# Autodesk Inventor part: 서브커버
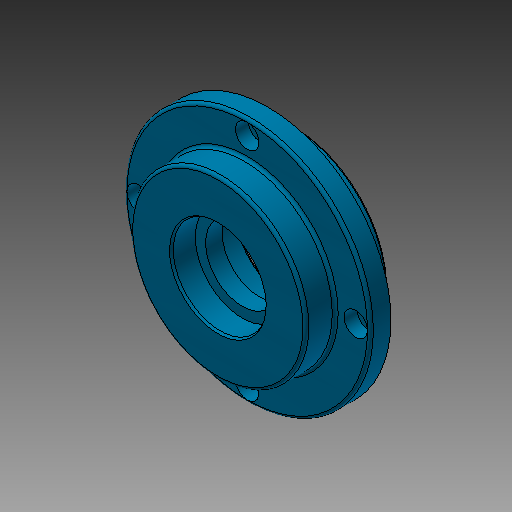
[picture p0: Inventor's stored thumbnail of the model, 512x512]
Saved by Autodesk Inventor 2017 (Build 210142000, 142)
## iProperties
Created: 2018-09
Part Number: 서브커버
Material: 알루미늄 6061
Document SubType Name: Modeling
Designer: mduedu
Density: 2.71 g/cm^3
Appearance: 하늘색 중간
Mass: 192.658 g
Surface Area: 184.057 cm^2
Volume: 71.0915 cm^3
Author: mduedu
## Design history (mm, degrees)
sketch "스케치1"
  geometry: C1 r 42 at (0, 0); 1 further point
  constraints: 1 centre point, 1 coincident
  dimensions: "d34" = 84 diameter of C1
extrude "돌출1" new body sketch "스케치1" distance "d2" = 7; taper "d3" = 0 deg
sketch "스케치2"
  geometry: C1 r 30 at (0, 0); 1 further point
  constraints: 1 centre point, 1 coincident
  dimensions: "d4" = 60 diameter of C1
extrude "돌출2" join sketch "스케치2" distance "d5" = 10; taper "d6" = 0 deg
sketch "스케치3"
  geometry: C1 r 32.5 at (0, 0); 1 further point
  constraints: 1 centre point, 1 coincident
  dimensions: "d7" = 65 diameter of C1
extrude "돌출3" join sketch "스케치3" distance "d8" = 9; taper "d9" = 0 deg
sketch "스케치4"
  geometry: L1 (-32.5, -9)-(32.5, -9) reference; L2 (30, 17)-(-30, 17) reference; L3 (0, 17)-(0, -9); L4 (0, -9)-(20, -9); L5 (20, -9)-(20, 3); L6 (20, 3)-(0, 3); L7 (0, 3)-(0, -9); L8 (0, 3)-(12.5, 3); L9 (12.5, 3)-(12.5, 8.7); L10 (12.5, 8.7)-(0, 8.7); L11 (0, 8.7)-(0, 3); L12 (0, 8.7)-(16, 8.7); L13 (16, 8.7)-(16, 17); L14 (16, 17)-(0, 17); L15 (0, 17)-(0, 8.7); 1 further point
  constraints: 26 end point, 6 parallel, 3 horizontal, 3 perpendicular, 2 midpoint, 1 point on line
  dimensions: "d10" = 12 distance of L4.end L5.end; "d12" = 8.3 distance of L12.end L13.end; "d13" = 32 diameter of L13 L3; "d14" = 25 diameter of L9 L3; "d15" = 40 diameter of L5 L3
revolve "회전1" sketch "스케치4" stored, may be unused: angle "d16" = 90 deg
fillet "모깎기2" dims "d18" = 1
fillet "모깎기3" dims "d19" = 1
chamfer "모따기1" distance "d20" = 0.8; stored, may be unused: second distance "d21" = 2, angle "d22" = 30 deg
chamfer "모따기2" distance "d23" = 1; stored, may be unused: second distance "d24" = 2, angle "d25" = 30 deg
fillet "모깎기4" dims "d26" = 0.3
sketch "스케치5" dims "d35" = 74
  geometry: 3 further points
  constraints: 2 vertical alignment, 1 coincident, 2 other
hole "구멍1" sketch "스케치5" at (0, 37) diameter "d27" = 4.5; stored, may be unused: countersink angle "d31" = 90 deg, drill point angle "d33" = 118 deg; dims "d28" = 6, "d29" = 8, "d30" = 4.4, "d32" = 8
node "솔리드1"
pattern_circular "원형 패턴1" dims angle "d37" = 360 deg
